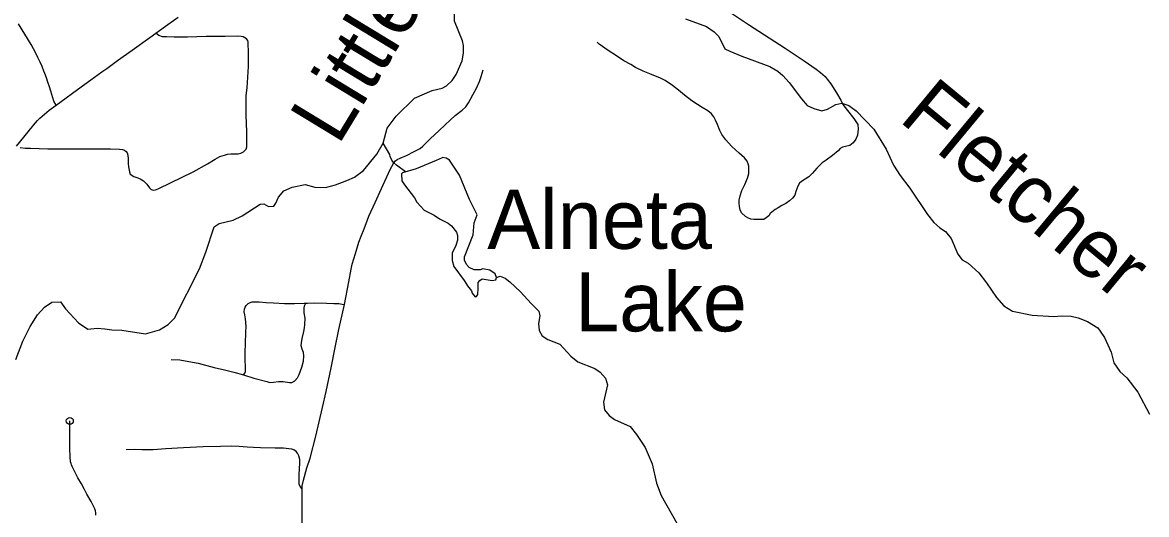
# Model space of a CAD drawing. Extents: x -19 to 366, y -4 to 359.
# Drawn here: x 139.407 to 140.926, y 193.112 to 193.777 of the extents above; entities that cross this region are included whole.
import ezdxf

# ---------------------------------------------------------------- set-up
doc = ezdxf.new("R2010")
doc.units = 0
for name, color, linetype in [('Level 31', 7, 'Continuous'), ('Level 32', 7, 'Continuous'), ('Level 35', 7, 'Continuous'), ('Level 60', 7, 'Continuous')]:
    doc.layers.add(name, color=color, linetype=linetype)

msp = doc.modelspace()

# ---------------------------------------------------------------- linework, layer by layer
at = {"layer": 'Level 31'}
for points in [[(139.5877, 193.7626), (139.5975, 193.7697), (139.6178, 193.7843)], [(140.3569, 193.7949), (140.3883, 193.7743), (140.4375, 193.7422), (140.4635, 193.7253), (140.4797, 193.7138), (140.4856, 193.7096), (140.4916, 193.7038), (140.4944, 193.7004), (140.4995, 193.6941), (140.5071, 193.6818), (140.5128, 193.672), (140.5155, 193.6663), (140.5218, 193.658), (140.5304, 193.6474), (140.5358, 193.6392), (140.5364, 193.6327), (140.5353, 193.6246), (140.5331, 193.6192)], [(139.4529, 193.6652), (139.4498, 193.6708), (139.4456, 193.684), (139.4438, 193.6901), (139.4419, 193.6962), (139.4399, 193.7022), (139.4377, 193.7082), (139.4365, 193.7113), (139.4339, 193.7175), (139.4312, 193.7236), (139.4283, 193.7296), (139.4253, 193.7356), (139.4222, 193.7415), (139.419, 193.7473), (139.4106, 193.7614), (139.4022, 193.7753)], [(139.5146, 193.7102), (139.5213, 193.715), (139.5358, 193.7255), (139.5555, 193.7396), (139.5795, 193.7567), (139.5877, 193.7626)], [(139.7098, 193.6781), (139.7111, 193.6887), (139.7118, 193.7032), (139.7126, 193.7177), (139.7126, 193.7351), (139.7125, 193.7502), (139.7117, 193.7528), (139.7102, 193.755), (139.7079, 193.7565), (139.7056, 193.7577), (139.7027, 193.7583), (139.6979, 193.7586), (139.6814, 193.7582), (139.6554, 193.758), (139.6303, 193.7573), (139.6122, 193.7574), (139.6019, 193.7575), (139.5968, 193.7577), (139.5916, 193.7593), (139.5877, 193.7626)], [(139.4529, 193.6652), (139.4598, 193.6703), (139.4819, 193.6865), (139.5, 193.6996), (139.5146, 193.7102)], [(139.8423, 193.3957), (139.8483, 193.4266), (139.8513, 193.4436), (139.853, 193.4504), (139.8571, 193.4649), (139.8619, 193.4801), (139.8651, 193.4883), (139.8692, 193.4982), (139.8735, 193.51), (139.8754, 193.5152), (139.8838, 193.5337), (139.8926, 193.5526), (139.9043, 193.5781), (139.909, 193.5872), (139.9112, 193.5902), (139.9137, 193.5916), (139.9178, 193.5934), (139.9261, 193.5974), (139.9364, 193.6026), (139.9445, 193.6067), (139.9482, 193.61), (139.9583, 193.6196), (139.9702, 193.631), (139.9857, 193.6453), (139.9919, 193.6512), (140.0013, 193.6585), (140.0063, 193.6628), (140.0098, 193.6682), (140.016, 193.679), (140.0208, 193.6883), (140.0249, 193.6972), (140.0272, 193.7042), (140.0297, 193.7128)], [(139.3994, 193.6096), (139.4208, 193.6364), (139.4224, 193.6383), (139.4251, 193.6415), (139.4279, 193.6446), (139.4308, 193.6476), (139.4339, 193.6505), (139.437, 193.6532), (139.4402, 193.6559), (139.4435, 193.6584), (139.4529, 193.6652)], [(139.8179, 193.2783), (139.8245, 193.3103), (139.83, 193.3377), (139.835, 193.3621), (139.8423, 193.3957)], [(139.7854, 193.1463), (139.7853, 193.1507), (139.7872, 193.1581), (139.7915, 193.175), (139.7959, 193.1882), (139.8036, 193.2178), (139.8129, 193.2567), (139.8179, 193.2783)], [(139.5064, 193.1108), (139.5065, 193.1139), (139.5061, 193.117), (139.5052, 193.1196), (139.5001, 193.1294), (139.4945, 193.1393), (139.4912, 193.1458), (139.4871, 193.1534), (139.4824, 193.1614), (139.4781, 193.1697), (139.4746, 193.1768), (139.4738, 193.1788), (139.4731, 193.1809), (139.4725, 193.183), (139.4721, 193.1852), (139.4719, 193.1874), (139.4718, 193.1896), (139.4716, 193.2015), (139.4716, 193.2133), (139.4716, 193.2223), (139.4716, 193.2264), (139.4716, 193.23), (139.4714, 193.2383)], [(139.7854, 193.1463), (139.7825, 193.1498), (139.7812, 193.1527), (139.7811, 193.1561), (139.7814, 193.1657), (139.7823, 193.1811), (139.7819, 193.1864), (139.7808, 193.1912), (139.7791, 193.1946), (139.7771, 193.197), (139.7738, 193.1991), (139.7714, 193.2), (139.7674, 193.2007), (139.7602, 193.2014), (139.749, 193.2014), (139.729, 193.2019), (139.7193, 193.2023), (139.7109, 193.2029), (139.7, 193.2038), (139.6899, 193.204), (139.675, 193.2036), (139.6516, 193.2031), (139.625, 193.202), (139.6013, 193.2006), (139.5838, 193.1994), (139.5749, 193.1992), (139.5686, 193.1992), (139.5594, 193.1995), (139.5476, 193.1994)], [(139.7854, 193.0942), (139.7852, 193.1136), (139.7854, 193.1286), (139.7854, 193.1463)]]:
    msp.add_lwpolyline(points, dxfattribs=at)
msp.add_circle((139.4714, 193.2383), 0.00473, dxfattribs=at)
at = {"layer": 'Level 32'}
for points in [[(140.3462, 193.639), (140.3438, 193.6449), (140.3414, 193.6495), (140.3381, 193.6533), (140.3331, 193.6575), (140.3256, 193.6622), (140.3194, 193.666), (140.3116, 193.6711), (140.3019, 193.6786), (140.2935, 193.6855), (140.2853, 193.6919), (140.2756, 193.6985), (140.2682, 193.7021), (140.2605, 193.7054), (140.2547, 193.7074), (140.2459, 193.7113), (140.2354, 193.7162), (140.2291, 193.7201), (140.22, 193.7253), (140.21, 193.7319), (140.1988, 193.7391), (140.1866, 193.7476), (140.1839, 193.7506)], [(139.4044, 193.6082), (139.411, 193.607), (139.4181, 193.607), (139.4418, 193.6063), (139.4749, 193.6061), (139.5046, 193.6062), (139.5264, 193.6061), (139.5385, 193.6059), (139.5427, 193.6053), (139.5452, 193.6043), (139.5475, 193.6026), (139.5489, 193.6006), (139.5497, 193.5978), (139.5504, 193.5925), (139.5502, 193.5862), (139.5506, 193.5819), (139.5519, 193.5753), (139.5529, 193.5721), (139.5577, 193.5688), (139.5619, 193.5676), (139.5663, 193.5658), (139.5708, 193.5628), (139.5755, 193.5583), (139.5789, 193.5535), (139.5812, 193.5513), (139.5842, 193.5505), (139.5872, 193.5506), (139.5915, 193.5525), (139.6076, 193.5601), (139.6378, 193.5753), (139.6575, 193.5857), (139.6678, 193.5922), (139.6739, 193.5957), (139.6804, 193.5978), (139.6845, 193.5988), (139.6891, 193.5994), (139.6937, 193.5996), (139.699, 193.5996), (139.7025, 193.6005), (139.706, 193.6021), (139.7094, 193.6059), (139.7104, 193.6089), (139.7104, 193.6136), (139.7104, 193.6293), (139.7098, 193.6519), (139.7096, 193.6701), (139.7098, 193.6781)], [(140.5331, 193.6192), (140.5298, 193.6141), (140.5251, 193.6107), (140.5152, 193.6085), (140.512, 193.6066), (140.5091, 193.6033), (140.5017, 193.5973), (140.4929, 193.591), (140.4879, 193.5872), (140.4853, 193.5849), (140.4805, 193.5801), (140.4741, 193.573), (140.4695, 193.5685), (140.4647, 193.5653), (140.4598, 193.5621), (140.4569, 193.5596), (140.4549, 193.5557), (140.4523, 193.5487), (140.4506, 193.5437), (140.4477, 193.5397), (140.4434, 193.5358), (140.4386, 193.5324), (140.4333, 193.5296), (140.4282, 193.5266), (140.4242, 193.5243), (140.4199, 193.5208), (140.4174, 193.5186), (140.4155, 193.5158), (140.4122, 193.5127), (140.4088, 193.5105), (140.4006, 193.5105), (140.3955, 193.5105), (140.3915, 193.5112), (140.3873, 193.5129), (140.3843, 193.5147), (140.3789, 193.5197), (140.3768, 193.5238), (140.376, 193.5284), (140.3756, 193.5327), (140.3755, 193.5369), (140.3768, 193.5426), (140.3793, 193.5498), (140.3834, 193.5579), (140.3869, 193.5664), (140.3887, 193.573), (140.3887, 193.5788), (140.3887, 193.5827), (140.3877, 193.5861), (140.3862, 193.5896), (140.383, 193.5942), (140.3756, 193.6005), (140.3657, 193.6092), (140.361, 193.6143), (140.3576, 193.6184), (140.3549, 193.6219), (140.3521, 193.6256), (140.3494, 193.6311), (140.3462, 193.639)], [(139.7061, 193.3005), (139.7077, 193.3028), (139.7085, 193.3052), (139.7086, 193.3098), (139.7084, 193.3225), (139.7082, 193.3322), (139.7088, 193.3421), (139.7092, 193.3593), (139.7095, 193.3656), (139.7093, 193.3714), (139.7087, 193.3763), (139.7078, 193.3817), (139.7071, 193.386), (139.7072, 193.3893), (139.7081, 193.3923), (139.7098, 193.3946), (139.7125, 193.3971), (139.7143, 193.3981), (139.7175, 193.3992), (139.7208, 193.3994), (139.7272, 193.3992), (139.7365, 193.3985), (139.7465, 193.3981), (139.7613, 193.3973), (139.7675, 193.3969), (139.7748, 193.397), (139.7878, 193.3974), (139.7904, 193.3976)], [(139.7061, 193.3005), (139.72, 193.2961), (139.7377, 193.2915), (139.7416, 193.2904), (139.7467, 193.2906), (139.7535, 193.2915), (139.7596, 193.2917), (139.7683, 193.2901), (139.7713, 193.2904), (139.7752, 193.2925), (139.7789, 193.2965), (139.7814, 193.3013), (139.7848, 193.311), (139.7871, 193.3191), (139.7873, 193.3265), (139.7872, 193.3307), (139.7853, 193.3355), (139.7841, 193.3399), (139.7843, 193.344), (139.7853, 193.3498), (139.7875, 193.3593), (139.7885, 193.3642), (139.7887, 193.3688), (139.7892, 193.3774), (139.7881, 193.3845), (139.7879, 193.3907), (139.7885, 193.3941), (139.7904, 193.3976)], [(139.7904, 193.3976), (139.7924, 193.3977), (139.8014, 193.3979), (139.8183, 193.3976), (139.8282, 193.397), (139.8346, 193.3969), (139.8393, 193.396), (139.8423, 193.3957)], [(139.6081, 193.3212), (139.6201, 193.3209), (139.6322, 193.3187), (139.6449, 193.3162), (139.6665, 193.3104), (139.6802, 193.3073), (139.693, 193.3043), (139.7061, 193.3005)]]:
    msp.add_lwpolyline(points, dxfattribs=at)
at = {"layer": 'Level 35'}
for points in [[(139.9371, 193.6748), (139.9607, 193.6851), (139.9742, 193.6884), (139.9802, 193.6915), (139.988, 193.6985), (139.9932, 193.7065), (140.0015, 193.7253), (140.0033, 193.7355), (140.0031, 193.7458), (140.0018, 193.7522), (139.9911, 193.7788), (139.9905, 193.7979), (139.9934, 193.8033), (140.0093, 193.8218), (140.0156, 193.8314), (140.0348, 193.8753), (140.0438, 193.904), (140.0471, 193.9275), (140.0457, 193.9427), (140.0402, 193.9615)], [(140.303, 193.7819), (140.3314, 193.7714), (140.342, 193.7646), (140.3481, 193.7582), (140.3561, 193.7415), (140.3629, 193.7381), (140.3792, 193.7317), (140.4171, 193.7175), (140.4277, 193.7111), (140.4345, 193.7054), (140.4433, 193.6959), (140.4596, 193.6736), (140.4676, 193.6649), (140.4763, 193.6608), (140.4873, 193.6578), (140.4948, 193.6597), (140.5061, 193.6662), (140.5141, 193.6678), (140.5239, 193.6648), (140.5338, 193.6576), (140.5573, 193.6326), (140.5741, 193.6058), (140.584, 193.5842), (140.5931, 193.5702), (140.6061, 193.5528), (140.63, 193.5172), (140.6384, 193.5066), (140.6468, 193.4995), (140.6543, 193.4945), (140.6619, 193.4851), (140.6711, 193.4639), (140.6768, 193.4563), (140.6848, 193.4514), (140.6992, 193.4386), (140.7098, 193.425), (140.7232, 193.4053), (140.733, 193.3939), (140.7448, 193.3868), (140.7713, 193.3812), (140.8008, 193.3794), (140.811, 193.3806), (140.8242, 193.3799), (140.8333, 193.3776), (140.8462, 193.3727), (140.8602, 193.3641), (140.8693, 193.3512), (140.8781, 193.3315), (140.8816, 193.3167), (140.8896, 193.305), (140.8994, 193.2967), (140.9143, 193.2774), (140.9299, 193.2475)], [(139.3984, 193.3215), (139.4081, 193.3463), (139.4176, 193.3658), (139.4279, 193.3819), (139.4372, 193.3923), (139.4473, 193.399), (139.459, 193.3992), (139.4656, 193.3898), (139.4833, 193.3711), (139.4955, 193.3626), (139.5084, 193.3636), (139.5186, 193.363), (139.528, 193.3613), (139.5416, 193.3611), (139.5735, 193.356), (139.5927, 193.3616), (139.6042, 193.3686), (139.6128, 193.3771), (139.6464, 193.4441), (139.655, 193.4666), (139.6665, 193.5006), (139.6733, 193.5053), (139.6921, 193.5098), (139.7044, 193.5157), (139.7283, 193.5316), (139.7333, 193.5317), (139.7397, 193.5284), (139.7469, 193.5289), (139.7499, 193.5328), (139.7531, 193.5408), (139.7605, 193.5496), (139.7718, 193.5544), (139.7891, 193.5581), (139.8024, 193.5545), (139.8168, 193.554), (139.8303, 193.5577), (139.8457, 193.5632), (139.8558, 193.568), (139.8681, 193.5769), (139.8862, 193.5988), (139.8947, 193.6138), (139.9, 193.634), (139.9122, 193.6505), (139.9371, 193.6748)], [(139.9248, 193.5751), (139.9127, 193.5839), (139.9086, 193.5878), (139.9063, 193.5911), (139.9043, 193.5958), (139.9037, 193.5985), (139.8947, 193.6138)], [(139.9212, 193.5741), (139.9193, 193.5722), (139.9197, 193.5631), (139.9235, 193.5574), (139.9369, 193.54), (139.9403, 193.5339), (139.9502, 193.5234), (139.9634, 193.5166), (139.9706, 193.5117), (139.9824, 193.5056), (139.9869, 193.5019), (139.9938, 193.4935), (139.9953, 193.489), (139.995, 193.4825), (139.9927, 193.4753), (139.9878, 193.4651), (139.9879, 193.4552), (139.9902, 193.4469), (140.0043, 193.428), (140.0084, 193.4208), (140.0138, 193.4143), (140.0149, 193.4109), (140.0191, 193.406), (140.0206, 193.4064), (140.0225, 193.4091), (140.0228, 193.4174), (140.0232, 193.4254), (140.0251, 193.428), (140.0284, 193.4303), (140.0417, 193.4281), (140.047, 193.4289), (140.0477, 193.4323), (140.0458, 193.4372), (140.0386, 193.4421), (140.0291, 193.444), (140.0257, 193.4428), (140.0174, 193.4428), (140.011, 193.4458), (140.0072, 193.4496), (140.0045, 193.4557), (140.0045, 193.4602), (140.0161, 193.4898), (140.0175, 193.5062), (140.0217, 193.5168), (140.0114, 193.5376), (139.9976, 193.5706), (139.9843, 193.591)], [(139.9212, 193.5741), (139.9397, 193.5795), (139.9669, 193.5909), (139.9748, 193.5944)], [(139.9843, 193.591), (139.9797, 193.5936), (139.9748, 193.5944)], [(140.0477, 193.4323), (140.0526, 193.4342), (140.0594, 193.4312), (140.0659, 193.4263), (140.0803, 193.4127), (140.0944, 193.3972), (140.105, 193.3866), (140.1065, 193.3805), (140.1043, 193.3699), (140.1055, 193.3604), (140.1093, 193.3532), (140.1169, 193.3483), (140.1332, 193.3419), (140.148, 193.3257), (140.1575, 193.3181), (140.1806, 193.3091), (140.1878, 193.3042), (140.195, 193.2963), (140.1977, 193.2872), (140.1925, 193.2636), (140.1937, 193.2534), (140.1998, 193.2455), (140.2073, 193.2402), (140.2282, 193.2308), (140.2369, 193.2202), (140.2487, 193.2024), (140.2579, 193.1804), (140.264, 193.1543), (140.2702, 193.1376), (140.2915, 193.1001)]]:
    msp.add_lwpolyline(points, dxfattribs=at)
at = {"layer": 'Level 60'}
for points in [[(146.7783, 1.697), (146.5788, 10.3131), (146.3785, 18.9294), (146.1776, 27.5458), (145.9759, 36.1624), (145.7736, 44.7791), (145.5705, 53.396), (145.3668, 62.013), (145.1624, 70.6301), (144.9572, 79.2474), (144.7514, 87.8648), (144.5449, 96.4823), (144.3377, 105.1), (144.1299, 113.7179), (143.9213, 122.3359), (143.712, 130.954), (143.5021, 139.5723), (143.2915, 148.1907), (143.0802, 156.8092), (142.8682, 165.4279), (142.6555, 174.0468), (142.4422, 182.6658), (142.2282, 191.2849), (142.0135, 199.9042), (141.7981, 208.5236), (141.582, 217.1432), (141.3653, 225.7629), (141.1479, 234.3828), (140.9298, 243.0028), (140.711, 251.623), (140.4916, 260.2433), (140.2715, 268.8638), (140.0508, 277.4844), (139.8293, 286.1051), (139.6072, 294.726), (139.3845, 303.3471), (139.161, 311.9683), (138.937, 320.5896), (138.7122, 329.2111), (138.4868, 337.8328), (138.2607, 346.4546)], [(139.4406, 1.5315), (139.2511, 10.1473), (139.0608, 18.7633), (138.8699, 27.3793), (138.6784, 35.9956), (138.4861, 44.6119), (138.2932, 53.2285), (138.0997, 61.8451), (137.9055, 70.4619), (137.7106, 79.0789), (137.5151, 87.6959), (137.319, 96.3132), (137.1221, 104.9306), (136.9247, 113.5481), (136.7265, 122.1658), (136.5278, 130.7836), (136.3283, 139.4016), (136.1282, 148.0197), (135.9275, 156.6379), (135.7261, 165.2564), (135.5241, 173.8749), (135.3214, 182.4936), (135.1181, 191.1125), (134.9141, 199.7315), (134.7095, 208.3506), (134.5043, 216.9699), (134.2984, 225.5894), (134.0919, 234.209), (133.8847, 242.8288), (133.6769, 251.4487), (133.4685, 260.0687), (133.2594, 268.6889), (133.0497, 277.3093), (132.8393, 285.9298), (132.6283, 294.5504), (132.4167, 303.1713), (132.2044, 311.7922), (131.9916, 320.4133), (131.778, 329.0346), (131.5639, 337.656), (131.3491, 346.2776)], [(0, 189.5162), (7.1121, 189.5206), (14.2243, 189.5339), (21.3364, 189.556), (28.4484, 189.5869), (35.5605, 189.6267), (42.6725, 189.6754), (49.7844, 189.7329), (56.8962, 189.7992), (64.0079, 189.8744), (71.1196, 189.9584), (78.2311, 190.0512), (85.3425, 190.1529), (92.4538, 190.2635), (99.5649, 190.3829), (106.6759, 190.5111), (113.7867, 190.6482), (120.8974, 190.7941), (128.0078, 190.9489), (135.1181, 191.1125), (142.2282, 191.2849), (149.338, 191.4662), (156.4476, 191.6563), (163.5569, 191.8553), (170.666, 192.0631), (177.7749, 192.2798), (184.8835, 192.5053), (191.9917, 192.7396), (199.0997, 192.9828), (206.2074, 193.2348), (213.3147, 193.4956), (220.4218, 193.7653), (227.5285, 194.0438), (234.6348, 194.3312), (241.7408, 194.6274), (248.8464, 194.9324), (255.9516, 195.2463), (263.0564, 195.569), (270.1608, 195.9005), (277.2648, 196.2409), (284.3683, 196.5901), (291.4715, 196.9481), (298.5741, 197.315), (305.6763, 197.6907), (312.7781, 198.0753), (319.8793, 198.4686), (326.9801, 198.8708), (334.0804, 199.2818), (341.1801, 199.7017)]]:
    msp.add_spline(points, degree=3, dxfattribs=at)

# ---------------------------------------------------------------- texts
at = {"layer": 'Level 35'}
for s, rotation, p in [('Little', 58.6889, (139.8339, 193.6095)), ('Fletcher', 320.3547, (140.5897, 193.6448))]:
    msp.add_text(s, height=0.08, rotation=rotation, dxfattribs=at).set_placement(p)
for s, p in [('Alneta', (140.0354, 193.471)), ('Lake', (140.1541, 193.3594))]:
    msp.add_text(s, height=0.08, dxfattribs=at).set_placement(p)

doc.saveas('drawing.dxf')
